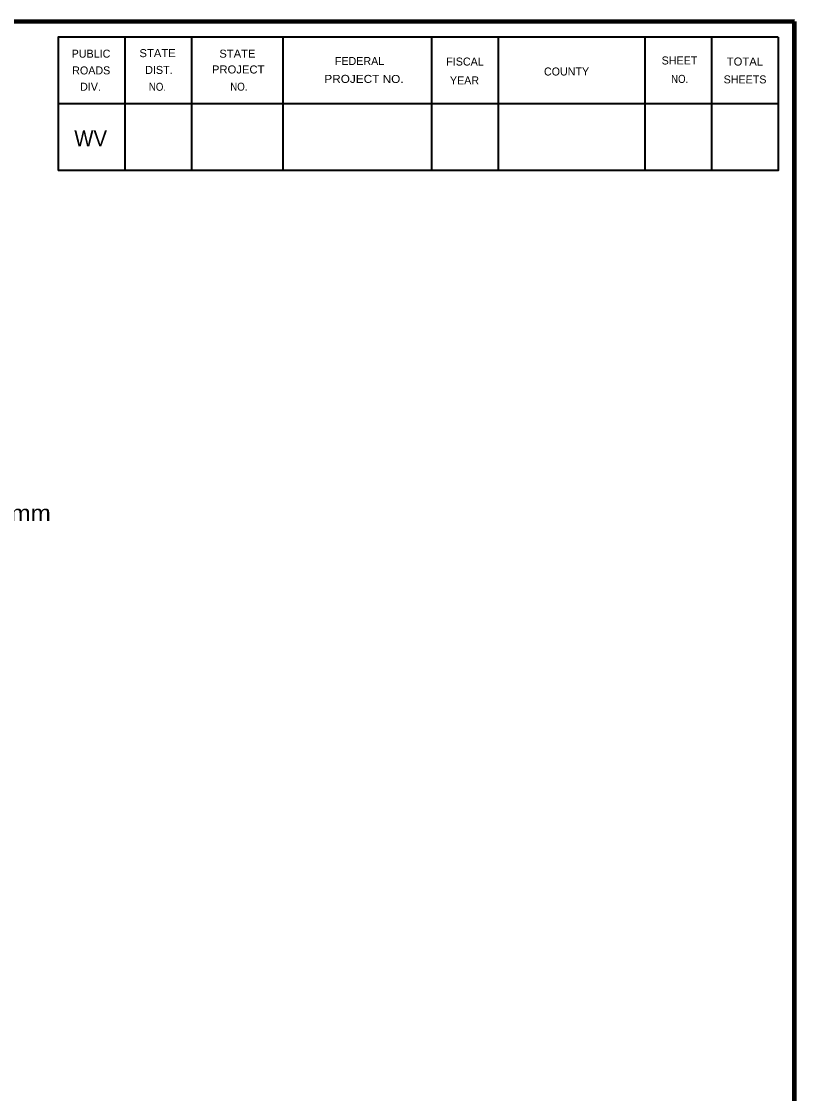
# Model space of a CAD drawing. Extents: x -105 to 751, y -65 to 479.
# Drawn here: x 597 to 744.1, y 268.5 to 472.7 of the extents above; entities that cross this region are included whole.
import ezdxf

# ---------------------------------------------------------------- set-up
doc = ezdxf.new("R2010")
doc.units = 0
doc.header["$LTSCALE"] = 1.2
doc.layers.add('1', color=7, linetype='Continuous', lineweight=35)
doc.layers.add('61', color=7, linetype='Continuous', lineweight=35)

msp = doc.modelspace()

# ---------------------------------------------------------------- linework, layer by layer
at = {"layer": '1', "lineweight": 158}
msp.add_line((744.128, -53.4), (744.128, 472.7), dxfattribs=at)
at = {"layer": '1', "lineweight": 13}
msp.add_line((744.128, -53.4), (744.128, 472.7), dxfattribs=at)
at = {"layer": '1', "lineweight": 158}
msp.add_lwpolyline([(744.128, 472.7), (-47.572, 472.6), (-47.472, -53.4)], dxfattribs=at)
at = {"layer": '61'}
for p, q in [((616.628, 469.7), (616.628, 444.3)), ((629.328, 469.7), (629.328, 444.3)), ((646.728, 469.7), (646.728, 444.3)), ((675.028, 469.7), (675.028, 444.3)), ((687.728, 469.7), (687.728, 444.3)), ((715.628, 469.7), (715.628, 444.3)), ((728.328, 469.7), (728.328, 444.3)), ((741.028, 457), (603.928, 457))]:
    msp.add_line(p, q, dxfattribs=at)
for points in [[(741.028, 469.7), (603.928, 469.7), (603.928, 444.3)], [(741.028, 469.7), (741.028, 444.3), (603.928, 444.3)]]:
    msp.add_lwpolyline(points, dxfattribs=at)

# ---------------------------------------------------------------- texts
at = {"layer": '1'}
for s, height, width, p in [('WV', 3.048, 0.95, (607.028, 448.9)), ('25mm', 3, 1.15, (589.739, 377.57))]:
    msp.add_text(s, height=height, dxfattribs=dict(at, width=width)).set_placement(p)
at = {"layer": '61'}
for s, height, rotation, p in [('PUBLIC', 1.525, 0.033, (606.528, 465.8)), ('FEDERAL', 1.523, 0.007, (656.628, 464.4)), ('FISCAL', 1.525, 359.942, (677.828, 464.3)), ('SHEET', 1.525, 0.059, (718.828, 464.5)), ('ROADS', 1.525, 0.124, (606.628, 462.6)), ('DIST.', 1.525, 0.056, (620.528, 462.7)), ('COUNTY', 1.523, 0.069, (696.428, 462.4)), ('YEAR', 1.523, 0.105, (678.528, 460.7)), ('SHEETS', 1.523, 359.959, (730.628, 460.9)), ('DIV.', 1.525, 359.932, (608.128, 459.5))]:
    msp.add_text(s, height=height, rotation=rotation, dxfattribs=at).set_placement(p)
for s, rotation, width, p in [('STATE', 0.059, 1.05, (619.428, 465.9)), ('STATE', 0.059, 1.05, (634.628, 465.8)), ('TOTAL', 359.926, 1.05, (731.228, 464.3)), ('PROJECT', 359.908, 1.05, (633.228, 462.8)), ('PROJECT NO.', 359.922, 1.1, (654.628, 461)), ('NO.', 359.852, 0.9, (720.628, 461)), ('NO.', 359.852, 0.9, (621.228, 459.5)), ('NO.', 0.225, 0.9, (636.728, 459.5))]:
    msp.add_text(s, height=1.525, rotation=rotation, dxfattribs=dict(at, width=width)).set_placement(p)

doc.saveas('drawing.dxf')
